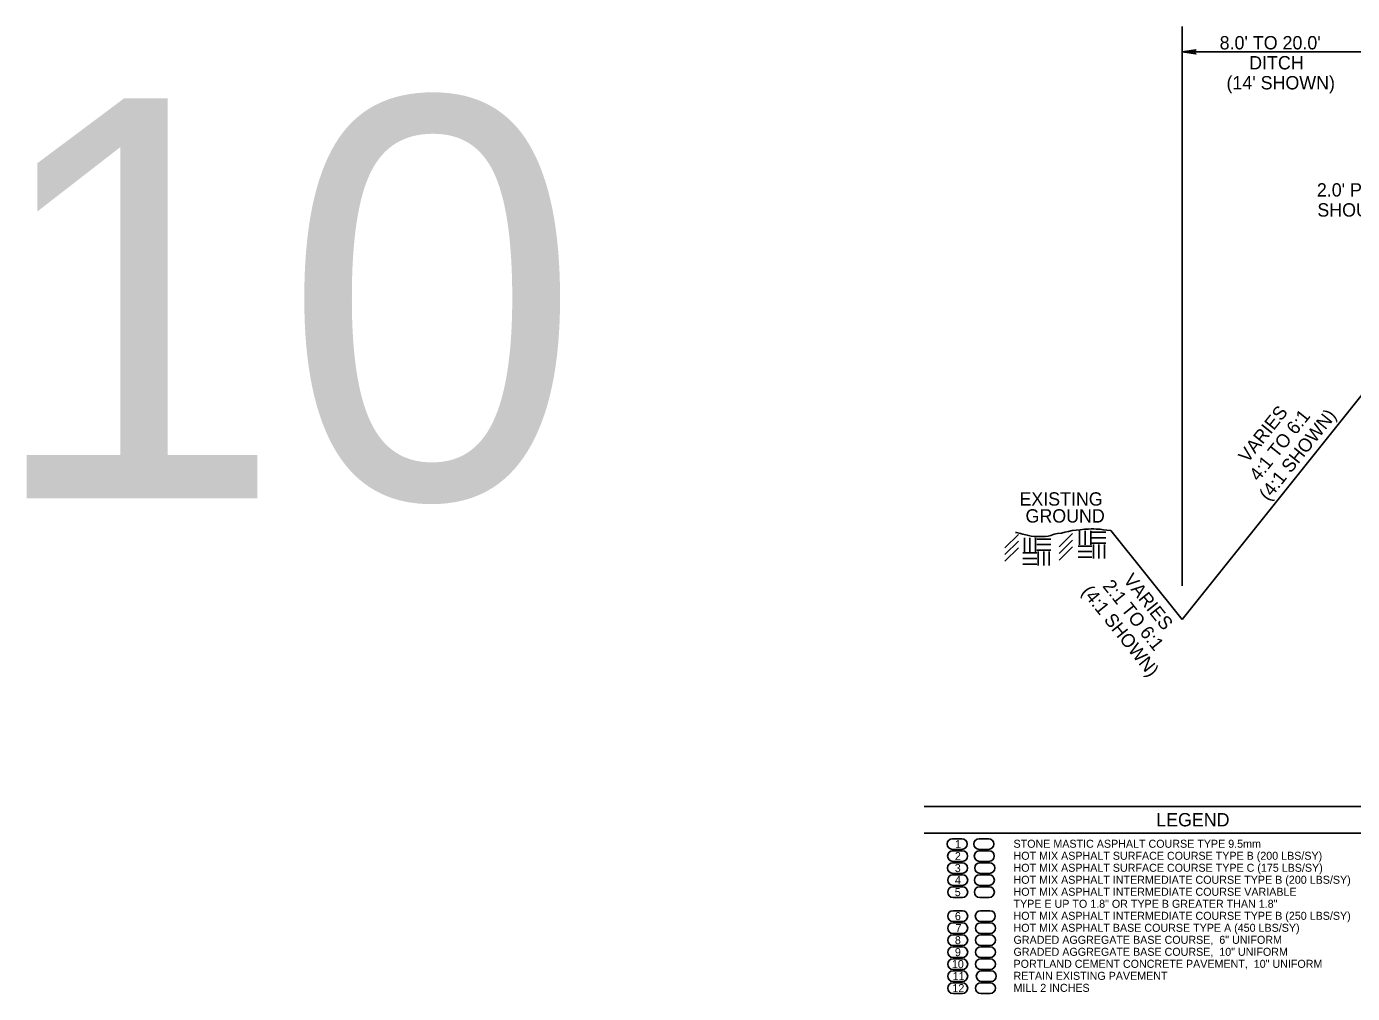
# Model space of a CAD drawing. Extents: x 2003207 to 2014043, y 843846 to 860154.
# Drawn here: x 2013548.4 to 2013647.8, y 843846.4 to 843918.9 of the extents above; entities that cross this region are included whole.
import ezdxf

# ---------------------------------------------------------------- set-up
doc = ezdxf.new("R2010")
doc.units = 0
for name, color, linetype in [('RD_EX_Road', 7, 'Continuous'), ('RD_EX_Road_txCode', 7, 'Continuous'), ('RD_QTY_ConcPave', 7, 'Continuous'), ('RD_QTY_Intermediate', 7, 'Continuous'), ('RD_QTY_Milling', 7, 'Continuous'), ('RD_QTY_PermVeg', 7, 'Continuous'), ('RD_QTY_Surf_Course', 7, 'Continuous'), ('RD_SHT_Bndy', 7, 'Continuous'), ('RD_SHT_TX', 7, 'Continuous'), ('RD_TX_Misc2', 7, 'Continuous'), ('RD_TX_TypSect', 7, 'Continuous'), ('RD_XS_ExGround', 7, 'Continuous')]:
    doc.layers.add(name, color=color, linetype=linetype)

msp = doc.modelspace()

# ---------------------------------------------------------------- linework, layer by layer
at = {"layer": 'RD_EX_Road'}
for p, q in [((2013620.723, 843848.087), (2013620.023, 843848.087)), ((2013620.661, 843847.187), (2013619.961, 843847.187)), ((2013620.023, 843847.287), (2013620.723, 843847.287)), ((2013619.961, 843846.387), (2013620.661, 843846.387))]:
    msp.add_line(p, q, dxfattribs=at)
for centre, start, end in [((2013620.023, 843847.687), 90, 270), ((2013620.723, 843847.687), 270, 90), ((2013619.961, 843846.787), 90, 270), ((2013620.661, 843846.787), 270, 90)]:
    msp.add_arc(centre, 0.4, start, end, dxfattribs=at)
at = {"layer": 'RD_EX_Road_txCode'}
msp.add_lwpolyline([(2013635.048, 843916.963), (2013636.087, 843916.813), (2013635.927, 843916.963), (2013636.087, 843917.113)], close=True, dxfattribs=at)
at = {"layer": 'RD_QTY_ConcPave'}
for p, q in [((2013620.661, 843850.787), (2013619.961, 843850.787)), ((2013619.961, 843849.987), (2013620.661, 843849.987)), ((2013620.661, 843849.887), (2013619.961, 843849.887)), ((2013619.961, 843849.087), (2013620.661, 843849.087)), ((2013620.661, 843848.987), (2013619.961, 843848.987)), ((2013619.961, 843848.187), (2013620.661, 843848.187))]:
    msp.add_line(p, q, dxfattribs=at)
for centre, start, end in [((2013619.961, 843850.387), 90, 270), ((2013620.661, 843850.387), 270, 90), ((2013619.961, 843849.487), 90, 270), ((2013619.961, 843848.587), 90, 270), ((2013620.661, 843849.487), 270, 90), ((2013620.661, 843848.587), 270, 90)]:
    msp.add_arc(centre, 0.4, start, end, dxfattribs=at)
at = {"layer": 'RD_QTY_Intermediate'}
for p, q in [((2013620.582, 843855.287), (2013619.882, 843855.287)), ((2013619.882, 843854.487), (2013620.582, 843854.487)), ((2013620.582, 843854.387), (2013619.882, 843854.387)), ((2013619.882, 843853.587), (2013620.582, 843853.587)), ((2013620.65, 843852.587), (2013619.95, 843852.587)), ((2013619.95, 843851.787), (2013620.65, 843851.787)), ((2013620.661, 843851.687), (2013619.961, 843851.687)), ((2013619.961, 843850.887), (2013620.661, 843850.887))]:
    msp.add_line(p, q, dxfattribs=at)
for centre, start, end in [((2013619.882, 843854.887), 90, 270), ((2013620.582, 843854.887), 270, 90), ((2013619.882, 843853.987), 90, 270), ((2013620.582, 843853.987), 270, 90), ((2013619.95, 843852.187), 90, 270), ((2013620.65, 843852.187), 270, 90), ((2013619.961, 843851.287), 90, 270), ((2013620.661, 843851.287), 270, 90)]:
    msp.add_arc(centre, 0.4, start, end, dxfattribs=at)
at = {"layer": 'RD_QTY_Milling'}
for p, q in [((2013620.661, 843847.187), (2013619.961, 843847.187)), ((2013619.961, 843846.387), (2013620.661, 843846.387))]:
    msp.add_line(p, q, dxfattribs=at)
for centre, start, end in [((2013619.961, 843846.787), 90, 270), ((2013620.661, 843846.787), 270, 90)]:
    msp.add_arc(centre, 0.4, start, end, dxfattribs=at)
at = {"layer": 'RD_QTY_PermVeg'}
for p in [(2013649.048, 843891.909), (2013629.712, 843881.08)]:
    msp.add_line(p, (2013635.048, 843874.409), dxfattribs=at)
at = {"layer": 'RD_QTY_Surf_Course'}
for p, q in [((2013620.542, 843857.987), (2013619.842, 843857.987)), ((2013619.842, 843857.187), (2013620.542, 843857.187)), ((2013620.576, 843857.087), (2013619.876, 843857.087)), ((2013619.876, 843856.287), (2013620.576, 843856.287)), ((2013620.61, 843856.187), (2013619.91, 843856.187)), ((2013619.91, 843855.387), (2013620.61, 843855.387))]:
    msp.add_line(p, q, dxfattribs=at)
for centre, start, end in [((2013619.842, 843857.587), 90, 270), ((2013620.542, 843857.587), 270, 90), ((2013619.876, 843856.687), 90, 270), ((2013620.576, 843856.687), 270, 90), ((2013619.91, 843855.787), 90, 270), ((2013620.61, 843855.787), 270, 90)]:
    msp.add_arc(centre, 0.4, start, end, dxfattribs=at)
at = {"layer": 'RD_SHT_Bndy'}
for p, q in [((2013655.72, 843860.41), (2013615.72, 843860.41)), ((2013655.72, 843858.41), (2013615.72, 843858.41))]:
    msp.add_line(p, q, dxfattribs=at)
at = {"layer": 'RD_TX_Misc2'}
for p, q in [((2013617.842, 843857.987), (2013618.542, 843857.987)), ((2013619.842, 843857.987), (2013620.542, 843857.987)), ((2013617.842, 843857.187), (2013618.542, 843857.187)), ((2013617.876, 843857.087), (2013618.576, 843857.087)), ((2013619.842, 843857.187), (2013620.542, 843857.187)), ((2013619.876, 843857.087), (2013620.576, 843857.087)), ((2013617.87, 843856.187), (2013618.57, 843856.187)), ((2013617.876, 843856.287), (2013618.576, 843856.287)), ((2013619.876, 843856.287), (2013620.576, 843856.287)), ((2013619.91, 843856.187), (2013620.61, 843856.187)), ((2013617.87, 843855.387), (2013618.57, 843855.387)), ((2013617.882, 843855.287), (2013618.582, 843855.287)), ((2013619.882, 843855.287), (2013620.582, 843855.287)), ((2013619.91, 843855.387), (2013620.61, 843855.387)), ((2013617.882, 843854.487), (2013618.582, 843854.487)), ((2013617.882, 843854.387), (2013618.582, 843854.387)), ((2013619.882, 843854.487), (2013620.582, 843854.487)), ((2013619.882, 843854.387), (2013620.582, 843854.387)), ((2013617.882, 843853.587), (2013618.582, 843853.587)), ((2013619.882, 843853.587), (2013620.582, 843853.587)), ((2013617.882, 843852.587), (2013618.582, 843852.587)), ((2013619.95, 843852.587), (2013620.65, 843852.587)), ((2013617.882, 843851.787), (2013618.582, 843851.787)), ((2013617.882, 843851.687), (2013618.582, 843851.687)), ((2013619.95, 843851.787), (2013620.65, 843851.787)), ((2013619.961, 843851.687), (2013620.661, 843851.687)), ((2013617.882, 843850.887), (2013618.582, 843850.887)), ((2013617.882, 843850.787), (2013618.582, 843850.787)), ((2013617.882, 843849.987), (2013618.582, 843849.987)), ((2013619.961, 843850.887), (2013620.661, 843850.887)), ((2013619.961, 843850.787), (2013620.661, 843850.787)), ((2013619.961, 843849.987), (2013620.661, 843849.987)), ((2013617.882, 843849.887), (2013618.582, 843849.887)), ((2013617.882, 843849.087), (2013618.582, 843849.087)), ((2013617.882, 843848.987), (2013618.582, 843848.987)), ((2013619.961, 843849.887), (2013620.661, 843849.887)), ((2013619.961, 843849.087), (2013620.661, 843849.087)), ((2013619.961, 843848.987), (2013620.661, 843848.987)), ((2013617.882, 843848.187), (2013618.582, 843848.187)), ((2013617.882, 843848.087), (2013618.582, 843848.087)), ((2013619.961, 843848.187), (2013620.661, 843848.187)), ((2013620.023, 843848.087), (2013620.723, 843848.087)), ((2013617.882, 843847.287), (2013618.582, 843847.287)), ((2013617.882, 843847.187), (2013618.582, 843847.187)), ((2013619.961, 843847.187), (2013620.661, 843847.187)), ((2013620.023, 843847.287), (2013620.723, 843847.287)), ((2013617.882, 843846.387), (2013618.582, 843846.387)), ((2013619.961, 843846.387), (2013620.661, 843846.387))]:
    msp.add_line(p, q, dxfattribs=at)
for centre, start, end in [((2013617.842, 843857.587), 90, 270), ((2013618.542, 843857.587), 270, 90), ((2013619.842, 843857.587), 90, 270), ((2013620.542, 843857.587), 270, 90), ((2013617.876, 843856.687), 90, 270), ((2013618.576, 843856.687), 270, 90), ((2013619.876, 843856.687), 90, 270), ((2013620.576, 843856.687), 270, 90), ((2013617.87, 843855.787), 90, 270), ((2013618.57, 843855.787), 270, 90), ((2013619.91, 843855.787), 90, 270), ((2013620.61, 843855.787), 270, 90), ((2013617.882, 843854.887), 90, 270), ((2013618.582, 843854.887), 270, 90), ((2013619.882, 843854.887), 90, 270), ((2013620.582, 843854.887), 270, 90), ((2013617.882, 843853.987), 90, 270), ((2013618.582, 843853.987), 270, 90), ((2013619.882, 843853.987), 90, 270), ((2013620.582, 843853.987), 270, 90), ((2013617.882, 843852.187), 90, 270), ((2013618.582, 843852.187), 270, 90), ((2013619.95, 843852.187), 90, 270), ((2013620.65, 843852.187), 270, 90), ((2013617.882, 843851.287), 90, 270), ((2013618.582, 843851.287), 270, 90), ((2013619.961, 843851.287), 90, 270), ((2013620.661, 843851.287), 270, 90), ((2013617.882, 843850.387), 90, 270), ((2013618.582, 843850.387), 270, 90), ((2013619.961, 843850.387), 90, 270), ((2013620.661, 843850.387), 270, 90), ((2013617.882, 843849.487), 90, 270), ((2013617.882, 843848.587), 90, 270), ((2013618.582, 843849.487), 270, 90), ((2013618.582, 843848.587), 270, 90), ((2013619.961, 843849.487), 90, 270), ((2013619.961, 843848.587), 90, 270), ((2013620.661, 843849.487), 270, 90), ((2013620.661, 843848.587), 270, 90), ((2013617.882, 843847.687), 90, 270), ((2013618.582, 843847.687), 270, 90), ((2013620.023, 843847.687), 90, 270), ((2013620.723, 843847.687), 270, 90), ((2013617.882, 843846.787), 90, 270), ((2013618.582, 843846.787), 270, 90), ((2013619.961, 843846.787), 90, 270), ((2013620.661, 843846.787), 270, 90)]:
    msp.add_arc(centre, 0.4, start, end, dxfattribs=at)
at = {"layer": 'RD_TX_TypSect'}
for p, q in [((2013635.048, 843876.948), (2013635.048, 843918.87)), ((2013635.048, 843916.963), (2013649.048, 843916.963))]:
    msp.add_line(p, q, dxfattribs=at)
at = {"layer": 'RD_XS_ExGround'}
for p, q in [((2013621.778, 843879.8), (2013622.778, 843880.8)), ((2013625.846, 843879.873), (2013626.846, 843880.873)), ((2013627.369, 843881.064), (2013627.369, 843880.022)), ((2013627.785, 843881.064), (2013627.785, 843880.022)), ((2013628.202, 843881.064), (2013628.202, 843880.022)), ((2013628.298, 843880.967), (2013629.34, 843880.967)), ((2013621.778, 843879.3), (2013622.778, 843880.3)), ((2013621.778, 843878.8), (2013622.778, 843879.8)), ((2013623.232, 843880.546), (2013623.232, 843879.504)), ((2013623.649, 843880.546), (2013623.649, 843879.504)), ((2013624.066, 843880.546), (2013624.066, 843879.504)), ((2013624.162, 843880.449), (2013625.204, 843880.449)), ((2013624.162, 843880.032), (2013625.204, 843880.032)), ((2013625.846, 843879.373), (2013626.846, 843880.373)), ((2013625.846, 843878.873), (2013626.846, 843879.873)), ((2013627.257, 843879.926), (2013628.298, 843879.926)), ((2013628.298, 843880.551), (2013629.34, 843880.551)), ((2013628.298, 843880.134), (2013629.34, 843880.134)), ((2013628.402, 843880.03), (2013628.402, 843878.988)), ((2013628.819, 843880.03), (2013628.819, 843878.988)), ((2013629.236, 843880.03), (2013629.236, 843878.988)), ((2013623.12, 843879.407), (2013624.162, 843879.407)), ((2013623.12, 843878.99), (2013624.162, 843878.99)), ((2013624.162, 843879.615), (2013625.204, 843879.615)), ((2013624.266, 843879.511), (2013624.266, 843878.47)), ((2013624.683, 843879.511), (2013624.683, 843878.47)), ((2013625.1, 843879.511), (2013625.1, 843878.47)), ((2013627.257, 843879.509), (2013628.298, 843879.509)), ((2013627.257, 843879.092), (2013628.298, 843879.092)), ((2013623.12, 843878.574), (2013624.162, 843878.574))]:
    msp.add_line(p, q, dxfattribs=at)
msp.add_lwpolyline([(2013622.574, 843880.952), (2013622.647, 843880.933), (2013622.94, 843880.86), (2013623.123, 843880.823), (2013623.452, 843880.75), (2013623.745, 843880.677), (2013623.965, 843880.64), (2013624.148, 843880.64), (2013624.367, 843880.64), (2013624.587, 843880.64), (2013624.807, 843880.64), (2013625.026, 843880.677), (2013625.209, 843880.713), (2013625.466, 843880.823), (2013625.722, 843880.86), (2013626.015, 843880.897), (2013626.271, 843880.97), (2013626.527, 843881.006), (2013626.82, 843881.08), (2013627.113, 843881.116), (2013627.406, 843881.153), (2013627.735, 843881.19), (2013628.028, 843881.19), (2013628.247, 843881.226), (2013628.43, 843881.226), (2013628.613, 843881.19), (2013628.906, 843881.19), (2013629.163, 843881.153), (2013629.419, 843881.116), (2013629.712, 843881.08)], dxfattribs=at)

# ---------------------------------------------------------------- texts
at = {"layer": 'RD_EX_Road_txCode'}
for s, height, p in [('LEGEND', 1, (2013633.11, 843858.91)), ('STONE MASTIC ASPHALT COURSE TYPE 9.5mm', 0.6, (2013622.417, 843857.31)), ('HOT MIX ASPHALT SURFACE COURSE TYPE B (200 LBS/SY)', 0.6, (2013622.417, 843856.41)), ('HOT MIX ASPHALT SURFACE COURSE TYPE C (175 LBS/SY)', 0.6, (2013622.417, 843855.51)), ('HOT MIX ASPHALT INTERMEDIATE COURSE TYPE B (200 LBS/SY)', 0.6, (2013622.417, 843854.61)), ('HOT MIX ASPHALT INTERMEDIATE COURSE VARIABLE ', 0.6, (2013622.417, 843853.71)), ('TYPE E UP TO 1.8" OR TYPE B GREATER THAN 1.8"', 0.6, (2013622.417, 843852.81)), ('HOT MIX ASPHALT INTERMEDIATE COURSE TYPE B (250 LBS/SY)', 0.6, (2013622.417, 843851.91)), ('HOT MIX ASPHALT BASE COURSE TYPE A (450 LBS/SY)', 0.6, (2013622.417, 843851.01)), ('GRADED AGGREGATE BASE COURSE,  6" UNIFORM', 0.6, (2013622.417, 843850.11)), ('GRADED AGGREGATE BASE COURSE,  10" UNIFORM', 0.6, (2013622.417, 843849.21)), ('PORTLAND CEMENT CONCRETE PAVEMENT,  10" UNIFORM', 0.6, (2013622.417, 843848.31)), ('RETAIN EXISTING PAVEMENT', 0.6, (2013622.417, 843847.41)), ('MILL 2 INCHES', 0.6, (2013622.417, 843846.51))]:
    msp.add_text(s, height=height, dxfattribs=at).set_placement(p)
at = {"layer": 'RD_SHT_TX'}
msp.add_text('10', height=30, dxfattribs=at).set_placement((2013545.368, 843883.492))
at = {"layer": 'RD_TX_Misc2'}
for s, p in [('1', (2013618.039, 843857.287)), ('2', (2013618.022, 843856.387)), ('3', (2013618.011, 843855.487)), ('4', (2013618.022, 843854.587)), ('5', (2013618.011, 843853.687)), ('6', (2013618.022, 843851.887)), ('7 ', (2013618.066, 843850.987)), ('8', (2013618.022, 843850.087)), ('9', (2013618.022, 843849.187)), ('10', (2013617.796, 843848.287)), ('11', (2013617.852, 843847.387)), ('12', (2013617.835, 843846.487))]:
    msp.add_text(s, height=0.6, dxfattribs=at).set_placement(p)
at = {"layer": 'RD_TX_TypSect'}
for s, p in [("8.0' TO 20.0'", (2013637.871, 843917.155)), ('DITCH', (2013640.083, 843915.655)), ("(14' SHOWN)", (2013638.383, 843914.155)), ("2.0' PAVED", (2013645.158, 843906.123)), ('SHOULDER', (2013645.197, 843904.623)), ('EXISTING', (2013622.859, 843882.955)), ('GROUND', (2013623.316, 843881.687))]:
    msp.add_text(s, height=1, dxfattribs=at).set_placement(p)
for s, rotation, p in [('VARIES', 51.34019, (2013639.97, 843886.107)), ('4:1 TO 6:1', 51.34019, (2013640.782, 843884.721)), ('(4:1 SHOWN)', 51.34019, (2013641.521, 843883.243)), ('VARIES', 308.65981, (2013630.604, 843877.363)), ('(4:1 SHOWN)', 308.65981, (2013627.469, 843876.479)), ('2:1 TO 6:1', 308.65981, (2013629.044, 843876.912))]:
    msp.add_text(s, height=1, rotation=rotation, dxfattribs=at).set_placement(p)

doc.saveas('drawing.dxf')
